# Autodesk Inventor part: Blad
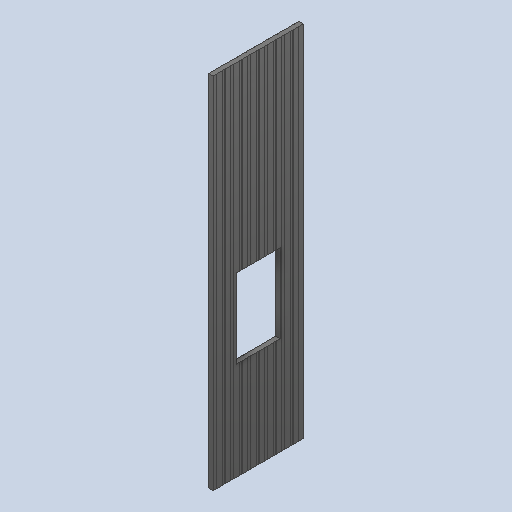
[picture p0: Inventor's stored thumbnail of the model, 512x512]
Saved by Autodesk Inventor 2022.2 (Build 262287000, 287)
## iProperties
Created: 2019-06
Part Number: Blad
Material: UHMW, Black
Document SubType Name: Modeling
Designer: cl
Density: 0.94 g/cm^3
Appearance: Smooth - Black
Author: cl
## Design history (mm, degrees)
sketch "Sketch4"
  geometry: L1 (0, 0)-(0, -35); L2 (0, -35)-(1.4, -36.4); L3 (1.4, -36.4)-(1.4, -96.4); L4 (1.4, -96.4)-(0, -97.8); L5 (0, 0)-(-23.6, 0); L6 (0, -97.8)-(-23.6, -97.8); L7 (-23.6, -97.8)-(-23.6, 0); L8 (-47.2, 0)-(-23.6, 0); L9 (-47.2, 0)-(-47.2, -35); L10 (-47.2, -35)-(-48.6, -36.4); L11 (-48.6, -36.4)-(-48.6, -96.4); L12 (-48.6, -96.4)-(-47.2, -97.8); L13 (-47.2, -97.8)-(-23.6, -97.8)
  constraints: 26 end point, 5 symmetric about line, 3 vertical, 2 horizontal
  dimensions: "d41" = 35 distance of L1.start L1.end; "d43" = 45 deg angle of L2 L1; "d44" = 60 distance of L2.end L3.end; "d45" = 45 deg angle of L3 L4; "d46" = 1.4 distance between parallel lines of L1 L3; "d47" = 1.4 horizontal distance of L3.end L4.end (derived); "d48" = 23.6 distance of L1.start L5.end
extrude "Extrusion2" new body sketch "Sketch4" distance "d49" = 3921 (derived); taper "d50" = 0 deg
sketch "Sketch5"
  geometry: L1 (-48.6, -96.4)-(-47.2, -97.8) reference; L2 (-47.2, -97.8)-(-47.2, -127.8); L3 (-47.2, -97.8)-(-17.2, -97.8); L4 (-47.2, -127.8)-(-48.6, -129.2); L5 (-48.6, -129.2)-(-48.6, -189.2); L6 (-47.2, -97.8)-(-23.6, -97.8); L7 (-47.2, -97.8)-(0, -97.8) reference; L8 (-23.6, -97.8)-(-23.6, -190.6); L9 (-48.6, -189.2)-(-47.2, -190.6); L10 (-47.2, -190.6)-(-23.6, -190.6); L11 (0, -97.8)-(-30, -97.8); L12 (0, -97.8)-(0, -127.8); L13 (0, -127.8)-(1.4, -129.2); L14 (1.4, -129.2)-(1.4, -189.2); L15 (0, -190.6)-(-23.6, -190.6); L16 (1.4, -189.2)-(0, -190.6); 1 further point
  constraints: 28 end point, 5 symmetric about line, 2 horizontal, 2 perpendicular, 2 vertical, 1 midpoint, 1 parallel
  dimensions: "d51" = 30 distance of L1.end L2.end; "d52" = 90 deg angle of L2 L3 (derived); "d54" = 1.4 distance between parallel lines of L2 L5; "d55" = 23.6 distance of L1.end L6.end; "d56" = 45 deg angle of L9 L5; "d57" = 1.4 distance from line of L5 L9.end; "d60" = 60 distance of L4.end L5.end
extrude "Extrusion3" join sketch "Sketch5" distance "d58" = 3921 (derived); taper "d59" = 0 deg
pattern_linear "Rectangular Pattern1" dims "d61" = 85.33405 (derived), "d63" = 92.8
sketch "Sketch7"
  geometry: L1 (-47.2, -855.9)-(0, -855.9); L2 (0, -855.9)-(0, -983.5); L3 (0, -983.5)-(-47.2, -983.5); L4 (-47.2, -983.5)-(-47.2, -855.9); L5 (0, 0)-(-47.2, 0) reference; L6 (-47.2, -97.8)-(-47.2, -127.8) reference; L7 (-47.2, -127.8)-(-48.6, -129.2) reference; L8 (-48.6, -129.2)-(-48.6, -189.2) reference; L9 (-48.6, -189.2)-(-47.2, -190.6) reference; L10 (-47.2, -190.6)-(-47.2, -220.6) reference; L11 (-47.2, -220.6)-(-48.6, -222) reference; L12 (-48.6, -222)-(-48.6, -282) reference; L13 (-48.6, -282)-(-47.2, -283.4) reference; L14 (-47.2, -283.4)-(-47.2, -313.4) reference; L15 (-47.2, -313.4)-(-48.6, -314.8) reference; L16 (-48.6, -314.8)-(-48.6, -374.8) reference; L17 (-48.6, -374.8)-(-47.2, -376.2) reference; L18 (0, -376.2)-(1.4, -374.8) reference; L19 (1.4, -374.8)-(1.4, -314.8) reference; L20 (1.4, -314.8)-(0, -313.4) reference; L21 (0, -313.4)-(0, -283.4) reference; L22 (0, -283.4)-(1.4, -282) reference; L23 (1.4, -282)-(1.4, -222) reference; L24 (1.4, -222)-(0, -220.6) reference; L25 (0, -220.6)-(0, -190.6) reference; L26 (0, -190.6)-(1.4, -189.2) reference; L27 (1.4, -189.2)-(1.4, -129.2) reference; L28 (1.4, -129.2)-(0, -127.8) reference; L29 (0, -127.8)-(0, -97.8) reference; L30 (-47.2, -35)-(-48.6, -36.4) reference; L31 (-48.6, -36.4)-(-48.6, -96.4) reference; L32 (-48.6, -96.4)-(-47.2, -97.8) reference; L33 (0, -97.8)-(1.4, -96.4) reference; L34 (1.4, -96.4)-(1.4, -36.4) reference; L35 (1.4, -36.4)-(0, -35) reference; L36 (0, -35)-(0, 0) reference; L37 (0, 0)-(-47.2, 0) reference; L38 (-47.2, 0)-(-47.2, -35) reference; L39 (-47.2, -376.2)-(-47.2, -406.2) reference; L40 (-47.2, -406.2)-(-48.6, -407.6) reference; L41 (-48.6, -407.6)-(-48.6, -467.6) reference; L42 (-48.6, -467.6)-(-47.2, -469) reference; L43 (-47.2, -469)-(-47.2, -499) reference; L44 (-47.2, -499)-(-48.6, -500.4) reference; L45 (-48.6, -500.4)-(-48.6, -560.4) reference; L46 (-48.6, -560.4)-(-47.2, -561.8) reference; L47 (0, -561.8)-(1.4, -560.4) reference; L48 (1.4, -560.4)-(1.4, -500.4) reference; L49 (1.4, -500.4)-(0, -499) reference; L50 (0, -499)-(0, -469) reference; L51 (0, -469)-(1.4, -467.6) reference; L52 (1.4, -467.6)-(1.4, -407.6) reference; L53 (1.4, -407.6)-(0, -406.2) reference; L54 (0, -406.2)-(0, -376.2) reference; L55 (-47.2, -561.8)-(-47.2, -591.8) reference; L56 (-47.2, -591.8)-(-48.6, -593.2) reference; L57 (-48.6, -593.2)-(-48.6, -653.2) reference; L58 (-48.6, -653.2)-(-47.2, -654.6) reference; L59 (0, -654.6)-(1.4, -653.2) reference; L60 (1.4, -653.2)-(1.4, -593.2) reference; L61 (1.4, -593.2)-(0, -591.8) reference; L62 (0, -591.8)-(0, -561.8) reference; L63 (-47.2, -654.6)-(-47.2, -684.6) reference; L64 (-47.2, -684.6)-(-48.6, -686) reference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
  constraints: 8 end point, 2 parallel, 1 horizontal, 1 perpendicular
  dimensions: "d67" = 983.5 distance between parallel lines of L5 L3 (derived)
extrude "Extrusion5" join sketch "Sketch7" distance "d68" = 3921 (derived); taper "d69" = 0 deg
sketch "Sketch10"
  geometry: L1 (155.35, 1932)-(635.35, 1932); L2 (635.35, 1932)-(635.35, 1070); L3 (635.35, 1070)-(155.35, 1070); L4 (155.35, 1070)-(155.35, 1932); L5 (395.35, 1070)-(395.35, 1932); L6 (155.35, 1070)-(635.35, 1070); L7 (635.35, 1070)-(635.35, 1932); L8 (635.35, 1932)-(155.35, 1932); L9 (155.35, 1932)-(155.35, 1070); L10 (395.35, 1932)-(395.35, 1070); 1 further point
  constraints: 20 end point, 4 midpoint, 4 parallel, 2 horizontal, 2 perpendicular, 1 collinear
  dimensions: "d82" = 862 distance of L1.end L2.end (derived); "d83" = 480 distance of L2.end L3.end (derived); "d86" = 491.75 distance from line of L5 point (-96.4, 0) (derived); "d92" = 1070 distance from line of point (-96.4, 0) L3 (derived); "d93" = 480 distance of L6.start L6.end (derived); "d94" = 862 distance of L6.end L7.end (derived); "d95" = 0.0001 distance between parallel lines of L3 L6 (derived)
extrude "Extrusion8" cut sketch "Sketch10" stored distance "d87" = 100; taper "d88" = 0 deg
body "Solid2"
node "Projected Loop1"
other parameters: "d24" = 45 deg, "BladBredd" = 987.5, "AntalVeck" = 9.88685 (computed from BladBredd) [user parameter], "Fönsterhöjd" = 862, "Blad2" = 1012.5, "Blad3" = 0, "Blad4" = 0, "Blad5" = 1012.5, "Blad6" = 2025, "MGJ12Djup" = 0, "MGJ12Bredd" = 0, "MGJ2Djup" = 0, "MGJ2Bredd" = 5012.5, "MGJ56Djup" = 0, "MGJ56Bredd" = 0, "MGJ23Djup" = 48, "MGJ45Djup" = 48, "GarageRegel5" = 0, "GarageRegel6" = 0, "Styrrulle2Djup" = 0, "FönsterhöjdStyrning" = 862, "FönsterKarm" = 54, "AndraGlasraden" = 0, "BrösthöjdStyrning2" = 0.0001
